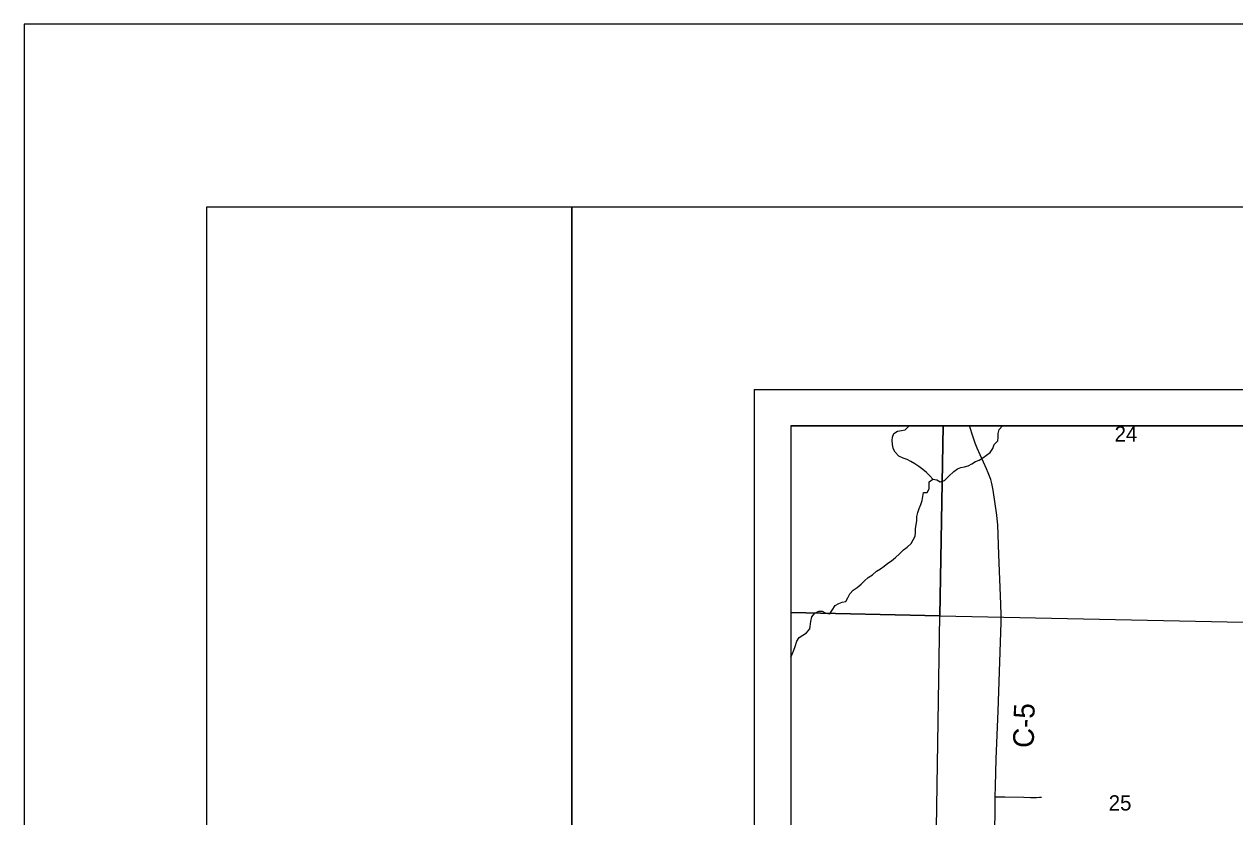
# Model space of a CAD drawing. Extents: x 0 to 34, y 0 to 22.
# Drawn here: x 0 to 3.317, y 19.83 to 22 of the extents above; entities that cross this region are included whole.
import ezdxf

# ---------------------------------------------------------------- set-up
doc = ezdxf.new("R2010")
doc.units = 0
for name, color, linetype in [('GM_X_Corporation', 7, 'Continuous'), ('GM_X_County_Road', 7, 'Continuous'), ('GM_X_County_Road_Text', 7, 'Continuous'), ('GM_X_Minor_River', 7, 'Continuous'), ('GM_X_Section_Text', 7, 'Continuous'), ('GM_X_Township_Road', 7, 'Continuous'), ('SH_Border', 7, 'Continuous'), ('SH_Cut_Line', 7, 'Continuous'), ('SH_Data', 7, 'Continuous')]:
    doc.layers.add(name, color=color, linetype=linetype)

msp = doc.modelspace()

# ---------------------------------------------------------------- linework, layer by layer
at = {"layer": 'GM_X_Corporation'}
for points in [[(2.5175, 20.9), (2.1, 20.9), (2.1, 20.3889), (2.5086, 20.3801)], [(3.5223, 20.9), (2.5175, 20.9), (2.5086, 20.3801), (3.5147, 20.359), (3.5146, 20.3904)], [(2.1, 20.3889), (2.1, 19.4012), (2.4933, 19.3936), (2.5086, 20.3801)], [(2.5086, 20.3801), (3.5147, 20.359), (3.4987, 19.3808), (2.4933, 19.3936)]]:
    msp.add_lwpolyline(points, close=True, dxfattribs=at)
msp.add_lwpolyline([(3.5231, 20.9), (2.1, 20.9), (2.1, 18.3932)], dxfattribs=at)
at = {"layer": 'GM_X_County_Road'}
msp.add_lwpolyline([(2.6586, 19.7245), (2.6603, 19.8512), (2.6605, 19.8842), (2.661, 19.9141), (2.6633, 19.9886), (2.668, 20.1196), (2.6751, 20.3084), (2.6766, 20.3624), (2.6768, 20.3817), (2.6758, 20.4122), (2.6701, 20.5481), (2.667, 20.6295), (2.6658, 20.6456), (2.6648, 20.6555), (2.6549, 20.7245), (2.6523, 20.738), (2.6505, 20.7459), (2.6482, 20.7536), (2.645, 20.7625), (2.6413, 20.7717), (2.6365, 20.7825), (2.628, 20.8005), (2.6186, 20.821), (2.6109, 20.839), (2.6055, 20.8529), (2.5996, 20.8693), (2.5896, 20.9)], dxfattribs=at)
at = {"layer": 'GM_X_Minor_River'}
for points in [[(2.4898, 20.7543), (2.4813, 20.7639), (2.4716, 20.7725), (2.4618, 20.7806), (2.4514, 20.7888), (2.4405, 20.7962), (2.4289, 20.8029), (2.4191, 20.8084), (2.4082, 20.812), (2.3965, 20.8171), (2.3861, 20.8287), (2.3809, 20.8383), (2.3789, 20.8498), (2.3783, 20.86), (2.3789, 20.8695), (2.3821, 20.8793), (2.3928, 20.8856), (2.4031, 20.8873), (2.4134, 20.8898), (2.4234, 20.8998), (2.4235, 20.9)], [(2.6685, 20.879), (2.6707, 20.8907), (2.6799, 20.9)], [(2.1, 20.2671), (2.1042, 20.2751), (2.1089, 20.286), (2.1118, 20.2966), (2.117, 20.3109), (2.1232, 20.3211), (2.1332, 20.3277), (2.1436, 20.334), (2.1521, 20.3445), (2.1548, 20.3649), (2.1581, 20.3774), (2.1658, 20.3879), (2.1766, 20.3934), (2.1864, 20.3932), (2.1962, 20.3877), (2.2068, 20.386), (2.2138, 20.3958), (2.2216, 20.4082), (2.2316, 20.4144), (2.2411, 20.4173), (2.2506, 20.419), (2.2561, 20.4292), (2.262, 20.4401), (2.2713, 20.4506), (2.2825, 20.4579), (2.2929, 20.4669), (2.3025, 20.4758), (2.3126, 20.4851), (2.3245, 20.4925), (2.3349, 20.5026), (2.3464, 20.5092), (2.3564, 20.5159), (2.3664, 20.524), (2.376, 20.5311), (2.3872, 20.5396), (2.3976, 20.55), (2.4092, 20.5608), (2.4192, 20.5679), (2.4296, 20.5779), (2.4359, 20.5881), (2.4406, 20.5979), (2.4416, 20.6081), (2.4422, 20.6187), (2.4439, 20.6305), (2.4456, 20.6407), (2.4458, 20.6521), (2.4479, 20.6635), (2.4519, 20.6744), (2.4567, 20.6853), (2.4603, 20.6963), (2.4624, 20.7069), (2.4641, 20.7175), (2.474, 20.7181), (2.4795, 20.7279), (2.4789, 20.7374), (2.4791, 20.7472), (2.4898, 20.7543), (2.5, 20.7526), (2.5098, 20.7474), (2.5212, 20.7506), (2.5336, 20.7629), (2.5471, 20.7756), (2.5567, 20.7823), (2.5663, 20.7863), (2.5762, 20.7884), (2.5861, 20.7912), (2.5961, 20.7964), (2.6064, 20.803), (2.616, 20.8066), (2.6263, 20.8129), (2.636, 20.8199), (2.646, 20.8273), (2.6541, 20.8382), (2.6577, 20.8492), (2.667, 20.8589), (2.668, 20.8687), (2.6685, 20.879)]]:
    msp.add_lwpolyline(points, dxfattribs=at)
at = {"layer": 'GM_X_Township_Road'}
msp.add_lwpolyline([(2.6605, 19.8842), (2.6866, 19.8842), (2.7388, 19.8833), (2.7574, 19.8829), (2.7736, 19.8829), (2.7816, 19.8834), (2.7873, 19.8833)], dxfattribs=at)
at = {"layer": 'SH_Border'}
for points in [[(0.5, 21.5), (1.5, 21.5), (1.5, 0.5), (0.5, 0.5)], [(1.5, 21.5), (33.5, 21.5), (33.5, 0.5), (1.5, 0.5)]]:
    msp.add_lwpolyline(points, close=True, dxfattribs=at)
at = {"layer": 'SH_Cut_Line'}
msp.add_lwpolyline([(0, 0), (34, 0), (34, 22), (0, 22)], close=True, dxfattribs=at)
at = {"layer": 'SH_Data'}
for p, q in [((2, 21), (9, 21)), ((2, 21), (2, 14)), ((2.1, 20.9), (2.1, 14.1)), ((2.1, 20.9), (8.9, 20.9)), ((2.1, 20.9), (2.1, 14.1)), ((2.1, 20.9), (8.9, 20.9)), ((2.1, 20.9), (2.1, 14.1)), ((2.1, 20.9), (8.9, 20.9))]:
    msp.add_line(p, q, dxfattribs=at)

# ---------------------------------------------------------------- texts
at = {"layer": 'GM_X_County_Road_Text'}
msp.add_text('C-5', height=0.05682, rotation=88.6255, dxfattribs=at).set_placement((2.7657, 20.018))
at = {"layer": 'GM_X_Section_Text'}
for s, p in [('24', (2.9874, 20.8574)), ('25', (2.9712, 19.8471))]:
    msp.add_text(s, height=0.04186, rotation=0, dxfattribs=at).set_placement(p)

doc.saveas('drawing.dxf')
